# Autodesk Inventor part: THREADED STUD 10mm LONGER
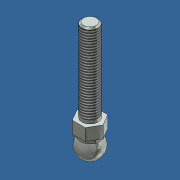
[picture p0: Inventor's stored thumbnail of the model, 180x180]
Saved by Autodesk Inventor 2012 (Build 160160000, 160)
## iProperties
Created: 2007-03
Part Number: THREADED STUD 10mm LONGER
Document SubType Name: Modeling
Designer: Andy Moles
Material: Steel
Mass: 52.5811 g
Surface Area: 26.5957 cm^2
Volume: 6.69823 cm^3
Density: 7.85 g/cm^3
Author: Andy Moles
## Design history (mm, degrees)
sketch "Sketch1"
  geometry: L1 (0, -7.5)-(0, 7.5); A1 r 7.5 centre (0, 0) between (0, -7.5) and (0, 7.5); 1 further point
  constraints: 2 end point, 2 point on circle, 1 centre point, 1 coincident, 1 midpoint, 1 vertical
  dimensions: "d5" = 15 distance of L1.start L1.end
revolve "Revolution1" sketch "Sketch1" stored, may be unused: angle "d1" = 90 deg
sketch "Sketch2"
  geometry: C1 r 6 at (0, 0); 1 further point
  constraints: 1 centre point, 1 coincident
  dimensions: "d2" = 12 diameter of C1
extrude "Extrusion1" join sketch "Sketch2" distance "d3" = 7; taper "d4" = 0 deg
sketch "Sketch3"
  geometry: L1 (-4.041, 7)-(4.041, 7); L2 (4.041, 7)-(8.083, 0); L3 (8.083, 0)-(4.041, -7); L4 (4.041, -7)-(-4.041, -7); L5 (-4.041, -7)-(-8.083, 0); L6 (-8.083, 0)-(-4.041, 7); C1 r 6 at (0, 0) reference; 1 further point
  constraints: 12 end point, 5 equal length, 1 horizontal, 1 horizontal alignment, 1 midpoint, 1 parallel, 1 vertical alignment
  dimensions: "d6" = 120 deg angle of L6 L5; "d7" = 120 deg angle of L1 L6; "d8" = 14 distance between parallel lines of L4 L1
extrude "Extrusion2" join sketch "Sketch3" distance "d9" = 7.5; taper "d10" = 0 deg
sketch "Sketch4"
  geometry: C1 r 5 at (0, 0); 1 further point
  constraints: 1 centre point, 1 coincident
  dimensions: "d11" = 10 diameter of C1
extrude "Extrusion3" join sketch "Sketch4" distance "d12" = 51.5; taper "d13" = 0 deg
thread "Thread1" dims "d14" = 49.5, "d15" = 2
chamfer "Chamfer1" distance "d16" = 1; stored, may be unused: second distance "d17" = 2, angle "d18" = 45 deg
body "Solid1"
